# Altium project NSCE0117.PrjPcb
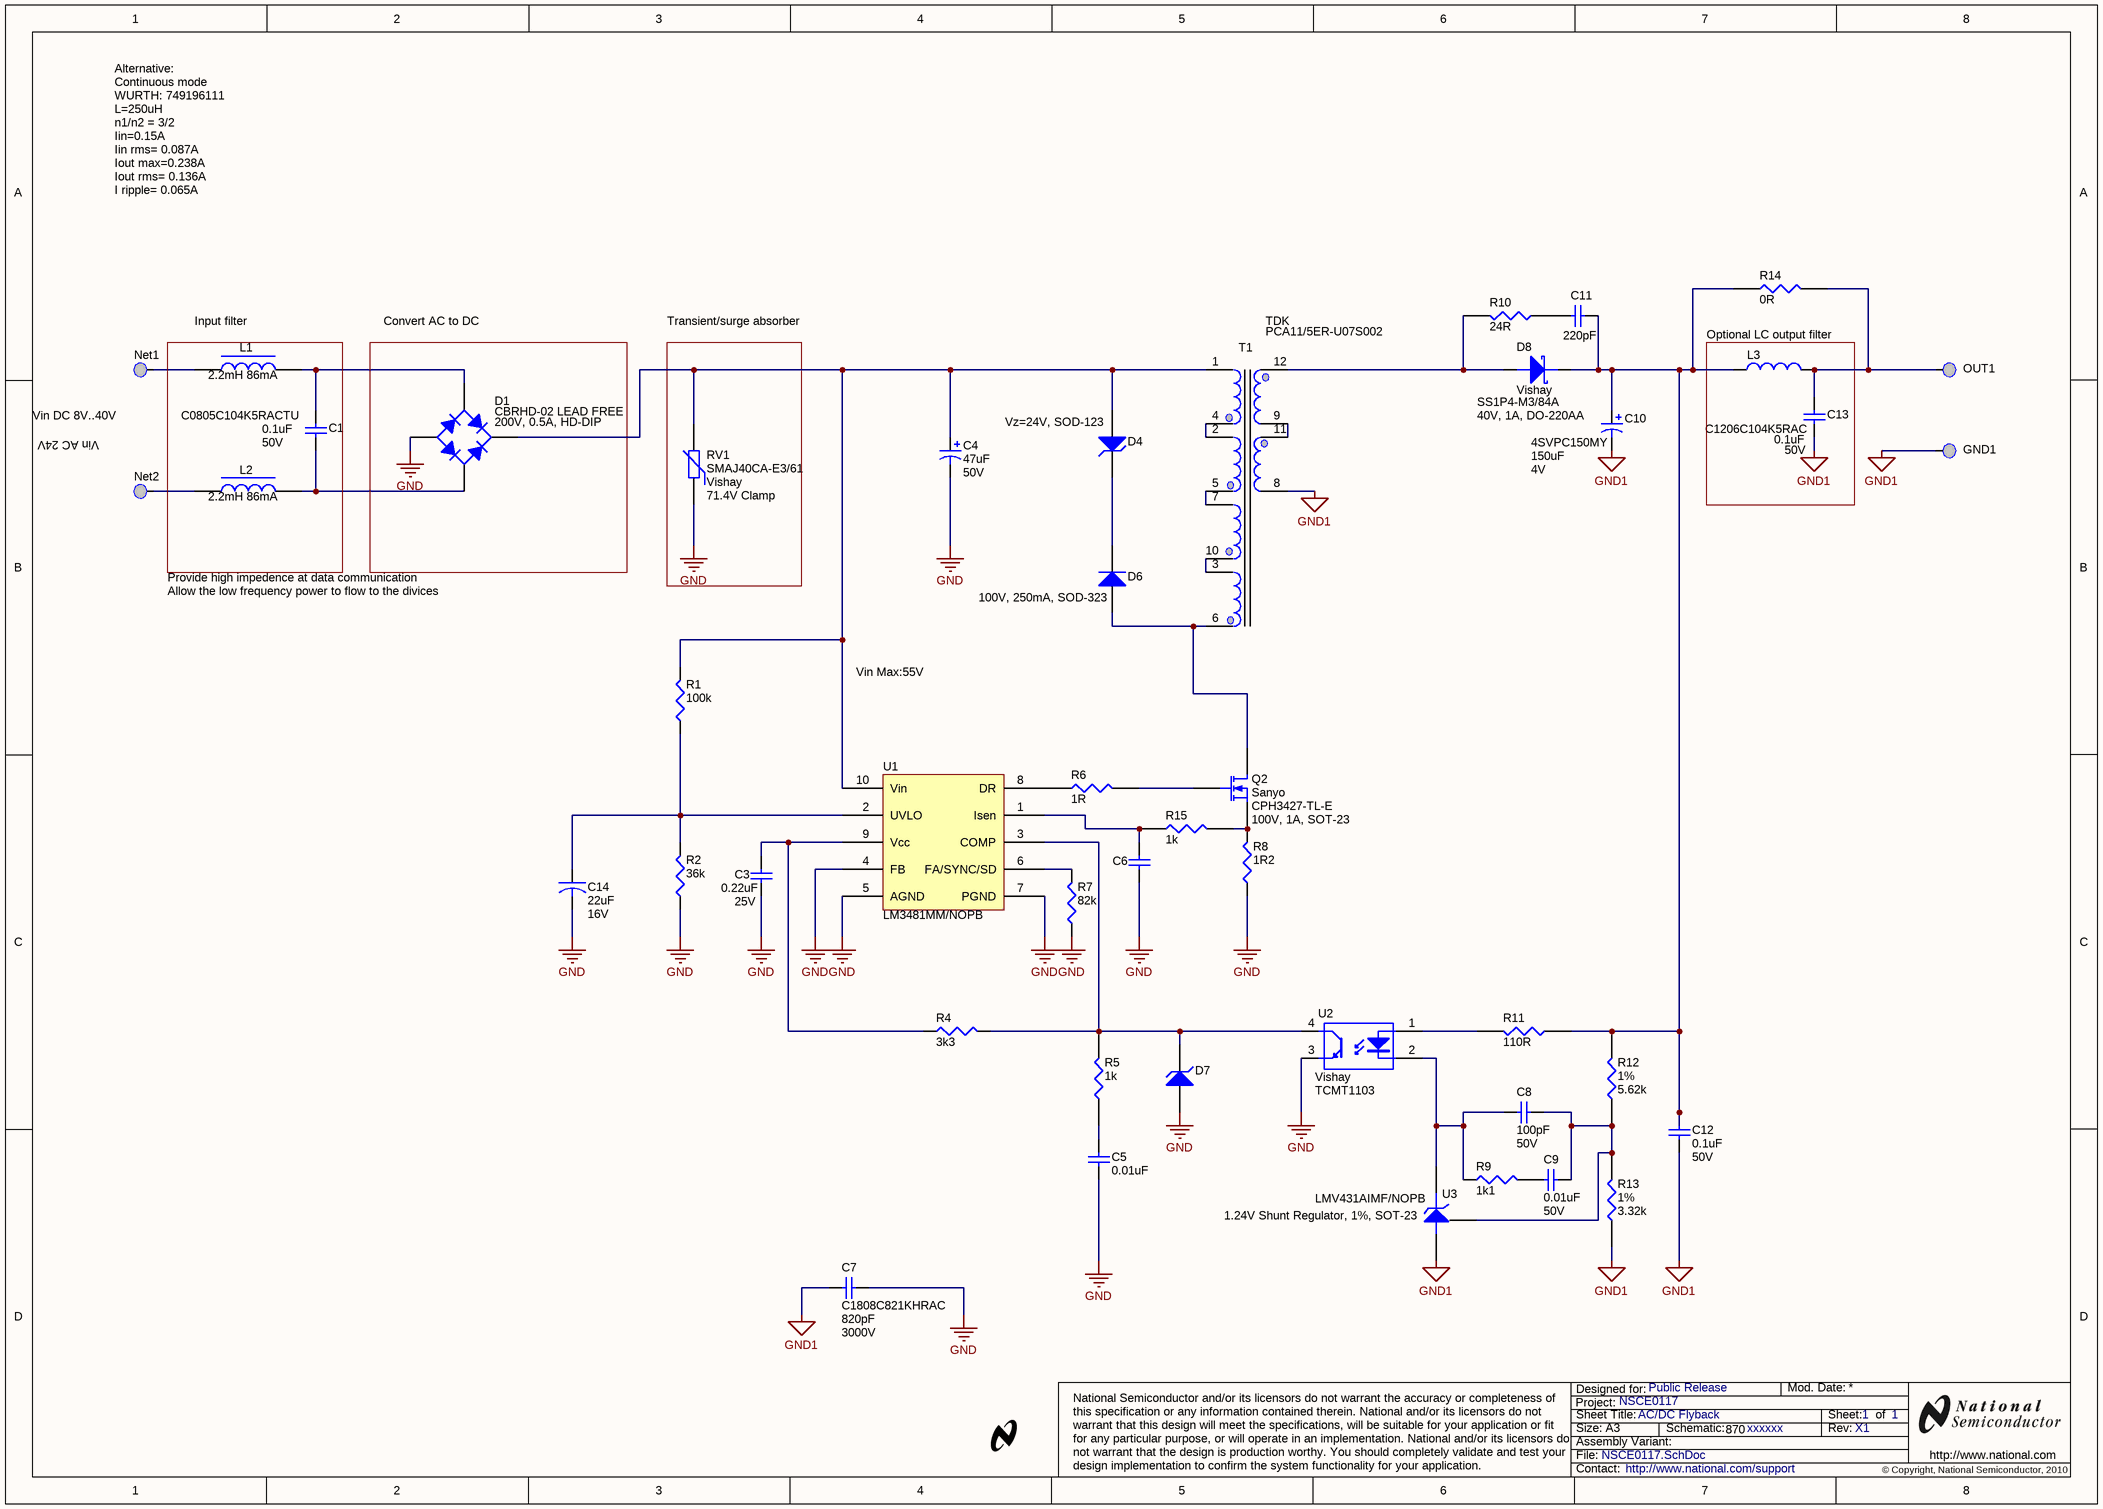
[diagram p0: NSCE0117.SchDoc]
PCB_MinorRev: -REV2; PRJ_BasePN: xxxxxx; PRJ_Customer: Public Release; PRJ_PADC: NSCE0117; PRJ_Title: NSCE0117; SCH_Rev: X1; TechSupport: http://www.national.com/support
1 sheet, 46 parts. Net scope: global (net labels, ports and power ports of the same name join across sheets).
Board file: NSCE0117.PcbDoc

## Sheet NSCE0117.SchDoc: AC/DC Flyback
size A3; DocumentNumber: 1; SheetNumber: 1; SheetTotal: 1; PageSetup: Record=PageOptions|CenterHorizontal=True|CenterVertical=True|PrintScale=0.71|XCorrection=1.00|YCorrection=1.00|PrintKind=1|BorderSize=5000000|LeftOffset=0|BottomOffset=0|Orientation=2|PaperLength=1000|PaperWidth=1000|Scale=100|PaperSource=15|PrintQuality=600|MediaType=300|DitherType=10|PaperKind=A4|PrintScaleMode=1

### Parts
C1  value 0.1uF  Vdc: 50V  [0805]  (hidden comment: C0805C104K5RACTU)
C3  value 0.22uF  Vdc: 25V  [0805]  (hidden comment: C0805C224K3RACTU)
C4  value 47uF  Vdc: 50V  [Panasonic E-Series AluCap]  (hidden comment: EEEFK1H470P)
C5  value 0.01uF  [0603]  (hidden comment: C0603C103K5RACTU)
C6  Not specified  [0603]  (value not drawn)
C7  value 820pF  Vdc: 3000V  [1808]  (hidden comment: C1808C821KHRAC)
C8  value 100pF  Vdc: 50V  [0603]  (hidden comment: C0603C101J5GAC)
C9  value 0.01uF  Vdc: 50V  [0603]  (hidden comment: C0603C103K5RACTU)
C10  value 150uF  Vdc: 4V  [OS-CON CaseB6 Sanyo]  (hidden comment: 4SVPC150MY)
C11  value 220pF  [0805]  (hidden comment: C0805C221J1GAC)
C12  value 0.1uF  Vdc: 50V  [0603]  (hidden comment: C0805C104K5RAC)
C13  value 0.1uF  Vdc: 50V  [1206]  (hidden comment: C1206C104K5RAC)
C14  value 22uF  Vdc: 16V  [1210]  (hidden comment: C1210C226K4PAC)
D1  CBRHD-02 LEAD FREE  Description: 200V, 0.5A, HD-DIP  [Optocoupler CBRHD-xx Central]
D4  Description: Vz=24V, SOD-123  [SOD-123]  (hidden comment: CMHZ4709 LEAD FREE)
D6  Description: 100V, 250mA, SOD-323  [sod-323]  (hidden comment: CMDD4448 LEAD FREE)
D7  CMOZ4L7 LEAD FREE  [SOD-523]  (value not drawn)
D8  Manufacturer: Vishay  Description: 40V, 1A, DO-220AA  [DO-220AA]  (hidden comment: SS1P4-M3/84A)
GND1  (no value)  [PCBPin_GoldenNeedle]  (no BOM)
L1  LPS6235-225MLB  [Ind_LPS6235]  (value not drawn)
L2  LPS6235-225MLB  [Ind_LPS6235]  (value not drawn)
L3  LPS4018-xxxMLB  [LPS4018 Coilcraft]  (value not drawn)
Logo1  (no value)  [Logo_Overlay_Medium]  (no BOM)
Net1  (no value)  [PCBPin_GoldenNeedle]  (no BOM)
Net2  (no value)  [PCBPin_GoldenNeedle]  (no BOM)
OUT1  (no value)  [PCBPin_GoldenNeedle]  (no BOM)
Q2  Manufacturer: Sanyo  Description: 100V, 1A, SOT-23  [SOT-23]  (hidden comment: CPH3427-TL-E)
R1  value 100k  [0603]
R2  value 36k  [0603]
R4  value 3k3  [0603]
R5  value 1k  [0603]
R6  value 1R  [0603]
R7  value 82k  [0603]
R8  value 1R2  [0805]
R9  value 1k1  [0603]
R10  value 24R  [1206]
R11  value 110R  [0603]
R12  value 5.62k  Tolerance: 1%  [0603]
R13  value 3.32k  Tolerance: 1%  [0603]
R14  value 0R  [0603]
R15  value 1k  [0603]
RV1  value 71.4V Clamp  Manufacturer: Vishay  [SMA]  (hidden comment: SMAJ40CA-E3/61)
T1  Manufacturer: TDK  [XFMR-ER11/5 Series Wuerth]  (hidden comment: PCA11/5ER-U07S002)
U1  LM3481MM/NOPB  [MSOP-10]
U2  Manufacturer: Vishay  [SOP-8]  (hidden comment: TCMT1103)
U3  LMV431AIMF/NOPB  [SOT-23]

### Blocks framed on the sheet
Convert AC to DC: D1
Transient/surge absorber: RV1
Optional LC output filter: C13 L3

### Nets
GND: C3.2 C4.2 C5.1 C6.1 C7.1 C14.2 D1.1(A) D7.1(A) R2.1 R7.1 R8.1 RV1.1 U1.4(FB) U1.5(AGND) U1.7(PGND) U2.3
GND1: C7.2 C10.2 C12.1 C13.2 GND1.1 R13.1 T1.8 U3.3(A)
NetC1_1: C1.1 D1.2(C) L1.2
NetC1_2: C1.2 D1.4(C) L2.2
NetC3_1: C3.1 R4.1 U1.9(Vcc)
NetC4_1: C4.1 D1.3(K) D4.1(A) R1.2 RV1.2 T1.1 U1.10(Vin)
NetC5_2: C5.2 R5.1
NetC6_2: C6.2 R15.1 U1.1(Isen)
NetC8_1: C8.1 C9.1 R12.1 R13.2 U3.2(FB)
NetC8_2: C8.2 R9.1 U2.2(K) U3.1(K)
NetC9_2: C9.2 R9.2
NetC10_1: C10.1 C11.1 C12.2 D8.2(K) L3.1 R11.1 R12.2 R14.1
NetC11_2: C11.2 R10.1
NetC13_1: C13.1 L3.2 OUT1.1 R14.2
NetC14_1: C14.1 R1.1 R2.2 U1.2(UVLO)
NetD4_2: D4.2(K) D6.2(K)
NetD6_1: D6.1(A) Q2.1(D) T1.6
NetD7_2: D7.2(K) R4.2 R5.2 U1.3(COMP) U2.4
NetD8_1: D8.1(A) R10.2 T1.12
NetL1_1: L1.1 Net1.1
NetL2_1: L2.1 Net2.1
NetQ2_2: Q2.2(G) R6.2
NetQ2_3: Q2.3(S) R8.2 R15.2
NetR6_1: R6.1 U1.8(DR)
NetR7_2: R7.2 U1.6(FA/SYNC/SD)
NetR11_2: R11.2 U2.1(A)
NetT1_2: T1.2 T1.4
NetT1_3: T1.3 T1.10
NetT1_5: T1.5 T1.7
NetT1_9: T1.9 T1.11

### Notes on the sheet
- Alternative: Continuous mode
  WURTH: 749196111
  L=250uH
  n1/n2 = 3/2
  Iin=0.15A
  Iin rms= 0.087A
  Iout max=0.238A
  Iout rms= 0.136A
  I ripple= 0.065A
- Input filter
- (near L1) 2.2mH 86mA
- Vin DC 8V..40V
- Vin AC 24V
- (near L2) 2.2mH 86mA
- Provide high impedence at data communication
- Allow the low frequency power to flow to the divices
- Vin Max:55V

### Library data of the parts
C1 = Cap Semi: CAP, CERM, 0.1uF, 50V, 10%, X7R, 0805; Manufacturer: Kemet
C3 = Cap Semi: CAP, CERM, 0.22uF, 25V, 10%, X7R, 0805; Manufacturer: Kemet
C4 = T491C: CAP, AL, 47uF, 50V, +/-20%, 0.68 ohm, SMD; Manufacturer: Panasonic; Tolerance: 10%
C5 C9 = Cap Semi: CAP, CERM, 0.01uF, 50V, 10%, X7R, 0603; Manufacturer: Kemet
C6 = Cap: CAP, CERM, 0603
C7 = Cap: CAP, CERM, 820pF, 3000V, 10%, X7R, 1808; Manufacturer: Kemet
C8 = Cap Semi: CAP, CERM, 100pF, 50V, 5%, C0G/NP0, 0603; Manufacturer: Kemet
C10 = T491C: CAP, Conductive Polymer, 150uF, 4V , 20%, SMD; Manufacturer: Sanyo; Tolerance: 10%
C11 = Cap Semi: CAP, CERM, 220pF, 100V, 5%, C0G/NP0, 0805; Manufacturer: Kemet; Tolerance: 10%
C12 = Cap Semi: CAP, CERM, 0.1uF, 50V, 10%, X7R, 0603; Manufacturer: Kemet; PartNumber: C0603C104K5RAC
C13 = Cap Semi: CAP, CERM, 0.1uF, 50V, 10%, X7R, 1206; Manufacturer: Kemet
C14 = CAP-1210: CAP, CERM, 22uF, 16V, 10%, X5R, 1210; Manufacturer: Kemet
D1 = Bridge1: Diode, Switching-Bridge, 200V, 0.5A, HD-DIP; pin to pad: 1>4 2>1 4>2; Manufacturer: Central Semiconductor
D4 = D Zener: Diode, Zener, 24V, SOD-123; Manufacturer: Central Semiconductor
D6 = Diode 1N4001: Diode, High Speed Switching, 100V, 250mA, SOD-323; Manufacturer: Central Semiconductor
D7 = D Zener: Diode, Zener, 4.7V, SOD-523; Manufacturer: Central Semiconductor
D8 = DIODE-S-SMA: Diode, Schottky, 40V, 1A, DO-220AA/SMP
GND1 Net1 Net2 OUT1 = PAD70
L1 L2 = IND-LPS4018: Inductor, Shielded Drum Core, Ferrite, 2.2mH, 0.11A, 6.4 ohm, SMD; Manufacturer: Coilcraft; Tolerance: 20%
L3 = Inductor: Inductor, Shielded Drum Core, Ferrite, SMD; Manufacturer: Coilcraft; Code_IEC: 1005
Logo1 = NSC Logo: National Semiconductor logo or worldmark
Q2 = MOSFET-N: MOSFET, N-CH, 100V, 1A, SOT-23; pin to pad: 1>3 2>1 3>2; PackageDocument: 1995/1996
R1 = Res3: RES, 100k, 5%, 0603; Manufacturer: Not Specified
R2 = Res3: RES, 36k, 5%, 0603; Manufacturer: Not Specified
R4 = Res3: RES, 3k3, 5%, 0603; Manufacturer: Not Specified
R5 R15 = RES1206: RES, 1k, 5%, 0603; Manufacturer: Not Specified
R6 = RES1206: RES, 1R, 5%, 0603; Manufacturer: Not Specified
R7 = Res3: RES, 82k, 5%, 0603; Manufacturer: Not Specified
R8 = Res3: RES, 1R2, 5%, 0805; Manufacturer: Not Specified
R9 = Res3: RES, 1k1, 5%, 0603; Manufacturer: Not Specified
R10 = RES1206: RES, 24R, 5%, 1206; Manufacturer: Not Specified
R11 = RES1206: RES, 110R, 5%, 0603; Manufacturer: Not Specified
R12 = RES1206: RES, 5.62k, 1%, 0603; Manufacturer: Not Specified
R13 = RES1206: RES, 3.32k, 1%, 0603; Manufacturer: Not Specified
R14 = RES0603: RES, 0R, 5%, 0603; Manufacturer: Not Specified
RV1 = Res Varistor: Transient Suppressor, 71.4V, SMA
T1 = XFMR-NSCE0117: Transformer
U1 = LM3481: High Efficiency Low-Side N-Channel Controller for Switching Regulators; Manufacturer: National Semiconductor
U2 = OPTO-NEC-PS2501: Optocoupler, CTR 100% to 200%
U3 = LM431: 1.24V Shunt Regulator, 1%, SOT-23; pin to pad: 1>2 2>1; Manufacturer: National Semiconductor

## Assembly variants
-100A: not fitted C6 D7 L3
